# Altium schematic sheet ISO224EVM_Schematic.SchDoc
size 431 x 279 mm; Date: Not shown in title block; ApprovedBy: Not shown in title block; CheckedBy: Not shown in title block; Author: Not shown in title block; CompanyName: Not shown in title block; Engineer: Not shown in title block; Organization: Not shown in title block; Address1: Not shown in title block; Address2: Not shown in title block; Address3: Not shown in title block; Address4: Not shown in title block; DocumentNumber: 1; Revision: Use project parameter SCH_Rev; SheetNumber: 2; SheetTotal: 3; PageSetup: Record=PageOptions¦CenterHorizontal=True¦CenterVertical=True¦PrintScale=1.00¦XCorrection=1.00¦YCorrection=1.00¦PrintKind=0¦BorderSize=5000000¦LeftOffset=0¦BottomOffset=0¦Orientation=2¦PaperLength=1000¦PaperWidth=1000¦Scale=100¦PaperSource=15¦PrintQuality=600¦MediaType=1¦DitherType=10¦PaperKind=Letter¦PrintScaleMode=1
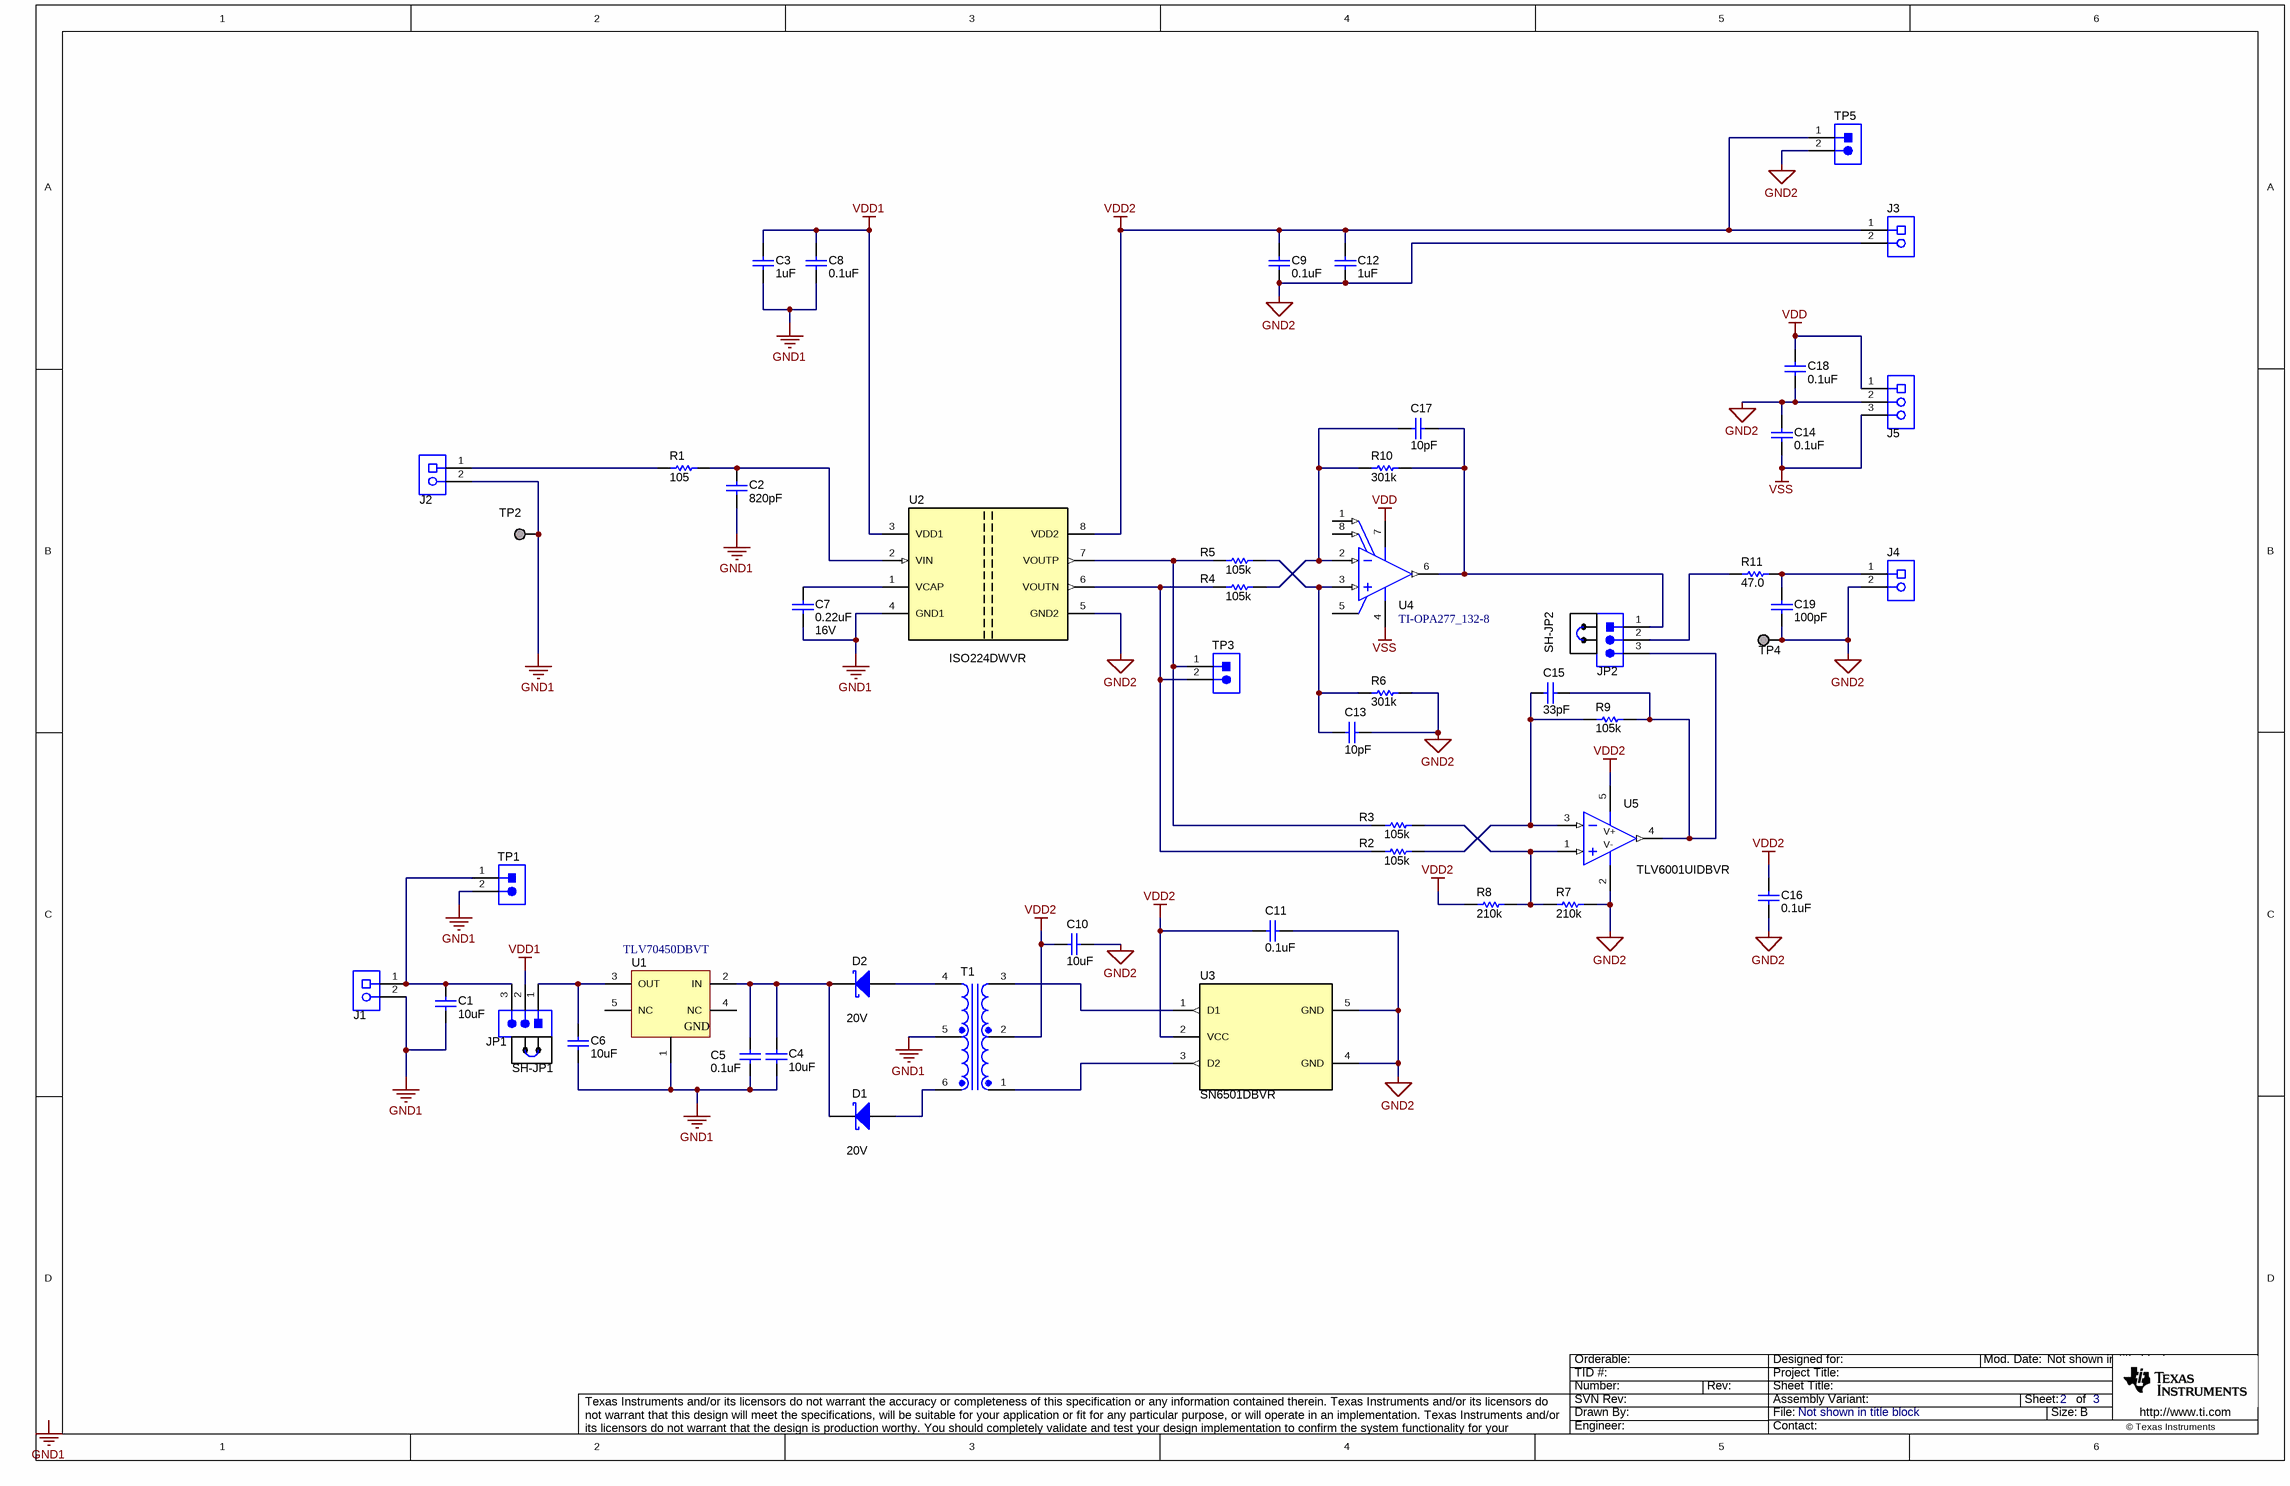
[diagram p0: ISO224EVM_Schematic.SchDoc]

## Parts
C1  ValueDisplayed: 10uF  [0805_HV]  (hidden comment: EMK212BJ106KG-T)
C2  ValueDisplayed: 820pF  [0805_HV]  (hidden comment: 08055A821JAT2A)
C3  ValueDisplayed: 1uF  [1206]  (hidden comment: 12063C105KAT2A)
C4  ValueDisplayed: 10uF  [0805_HV]  (hidden comment: EMK212BJ106KG-T)
C5  ValueDisplayed: 0.1uF  [0805_HV]  (hidden comment: C0805C104K3RACTU)
C6  ValueDisplayed: 10uF  [0805_HV]  (hidden comment: EMK212BJ106KG-T)
C7  ValueDisplayed: 0.22uF  VDC_V: 16V  [0603]  (hidden comment: 885012206048)
C8  ValueDisplayed: 0.1uF  [1206]  (hidden comment: 12061C104JAT2A)
C9  ValueDisplayed: 0.1uF  [1206]  (hidden comment: 12061C104JAT2A)
C10  ValueDisplayed: 10uF  [0805_HV]  (hidden comment: EMK212BJ106KG-T)
C11  ValueDisplayed: 0.1uF  [0603]  (hidden comment: 06033C104JAT2A)
C12  ValueDisplayed: 1uF  [1206]  (hidden comment: 12063C105KAT2A)
C13  ValueDisplayed: 10pF  [0603]  (hidden comment: C0603C100J5GACTU)
C14  ValueDisplayed: 0.1uF  [0603]  (hidden comment: 06033C104JAT2A)
C15  ValueDisplayed: 33pF  [0603]  (hidden comment: C0603C330J5GACTU)
C16  ValueDisplayed: 0.1uF  [0603]  (hidden comment: 06033C104JAT2A)
C17  ValueDisplayed: 10pF  [0603]  (hidden comment: C0603C100J5GACTU)
C18  ValueDisplayed: 0.1uF  [0603]  (hidden comment: 06033C104JAT2A)
C19  ValueDisplayed: 100pF  [0603]  (hidden comment: 0603ZC101KAT2A)
D1  value 20V  [SOD-123]  (hidden comment: MBR0520LT1G)
D2  value 20V  [SOD-123]  (hidden comment: MBR0520LT1G)
J1  ED555/2DS  [TERM_BLK_ED555-2DS]  (value not drawn)
J2  ED555/2DS  [TERM_BLK_ED555-2DS]  (value not drawn)
J3  ED555/2DS  [TERM_BLK_ED555-2DS]  (value not drawn)
J4  ED555/2DS  [TERM_BLK_ED555-2DS]  (value not drawn)
J5  ED555/3DS  [TERM_BLK_ED555-3DS]  (value not drawn)
JP1  TMM-103-01-T-S  [CONN_TMM-103-01-T-S]  (value not drawn)
JP2  TMM-103-01-T-S  [CONN_TMM-103-01-T-S]  (value not drawn)
R1  ValueDisplayed: 105  [0805_HV]  (hidden comment: CRCW0805105RFKEA)
R2  ValueDisplayed: 105k  [0603]  (hidden comment: CRCW0603105KFKEA)
R3  ValueDisplayed: 105k  [0603]  (hidden comment: CRCW0603105KFKEA)
R4  ValueDisplayed: 105k  [0603]  (hidden comment: CRCW0603105KFKEA)
R5  ValueDisplayed: 105k  [0603]  (hidden comment: CRCW0603105KFKEA)
R6  ValueDisplayed: 301k  [0603]  (hidden comment: CRCW0603301KFKEA)
R7  ValueDisplayed: 210k  [0603]  (hidden comment: RC0603FR-07210KL)
R8  ValueDisplayed: 210k  [0603]  (hidden comment: RC0603FR-07210KL)
R9  ValueDisplayed: 105k  [0603]  (hidden comment: CRCW0603105KFKEA)
R10  ValueDisplayed: 301k  [0603]  (hidden comment: CRCW0603301KFKEA)
R11  ValueDisplayed: 47.0  [0603]  (hidden comment: RC0603FR-0747RL)
SH-JP1  2SN-BK-G  [2SN-BK-G]  (value not drawn)
SH-JP2  2SN-BK-G  [2SN-BK-G]  (value not drawn)
T1  750313769  [WURTH_750313769]  (value not drawn)
TP1  TSW-102-07-G-S  [TSW-102-07-G-S]  (value not drawn)
TP2  1502-2  [Keystone1502-2]  (value not drawn)
TP3  TSW-102-07-G-S  [TSW-102-07-G-S]  (value not drawn)
TP4  1502-2  [Keystone1502-2]  (value not drawn)
TP5  TSW-102-07-G-S  [TSW-102-07-G-S]  (value not drawn)
U1  TLV70450DBVT  [DBV0005A_N]
U2  ISO224DWVR  [DWV0008A]
U3  SN6501DBVR  [DBV0005A_N]
U4  TI-OPA277_132-8  [D0008A_N]
U5  TLV6001UIDBVR  [DBV0005A_N]

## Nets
GND1: C1.2 C2.2 C3.2 C4.2 C5.2 C6.2 C7.2 C8.2 J1.2 J2.2 T1.5 TP1.2 TP2.1 U1.1(GND) U2.4(GND1)
GND2: C9.2 C10.1 C11.1 C12.2 C13.2 C14.2 C16.1 C18.1 C19.2 J3.2 J4.2 J5.2 R6.2 R7.2 TP4.1 TP5.2 U2.5(GND2) U3.4(GND) U3.5(GND) U5.2(V-)
VDD: C18.2 J5.1 U4.7(V+)
VDD1: C3.1 C8.1 JP1.2 U2.3(VDD1)
VDD2: C9.1 C10.2 C11.2 C12.1 C16.2 J3.1 R8.1 T1.2 TP5.1 U2.8(VDD2) U3.2(VCC) U5.5(V+)
VSS: C14.1 J5.3 U4.4(V-)
NetC1_1: C1.1 J1.1 JP1.3 TP1.1
NetC2_1: C2.1 R1.1 U2.2(VIN)
NetC4_1: C4.1 C5.1 D1.1(K) D2.1(K) U1.2(IN)
NetC6_1: C6.1 JP1.1 U1.3(OUT)
NetC7_1: C7.1 U2.1(VCAP)
NetC13_1: C13.1 R5.2 R6.1 U4.3(IN+)
NetC15_1: C15.1 R2.2 R9.1 U5.3(IN-)
NetC15_2: C15.2 JP2.3 R9.2 U5.4(OUT)
NetC17_1: C17.1 R4.2 R10.1 U4.2(IN-)
NetC17_2: C17.2 JP2.1 R10.2 U4.6(OUT)
NetC19_1: C19.1 J4.1 R11.2
NetD1_2: D1.2(A) T1.6
NetD2_2: D2.2(A) T1.4
NetJ2_1: J2.1 R1.2
NetJP2_2: JP2.2 R11.1
NetR2_1: R2.1 R4.1 TP3.2 U2.6(VOUTN)
NetR3_1: R3.1 R5.1 TP3.1 U2.7(VOUTP)
NetR3_2: R3.2 R7.1 R8.2 U5.1(IN+)
NetT1_1: T1.1 U3.3(D2)
NetT1_3: T1.3 U3.1(D1)

Not connected (* = marked no-connect by the designer): U1 4(NC) 5(NC); U4 1(OFFSET_TRIM) 5(NC) 8(OFFSET_TRIM)

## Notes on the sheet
- Labels drawn without touching a wire or pin: GND1

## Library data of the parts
C1 C4 C6 C10 = CMP-0008005-2: CAP, CERM, 10 uF, 16 V, +/- 10%, X5R, 0805; Manufacturer: Taiyo Yuden; Polarized: N; Value: 10uF; U/M: EA; Cap_F: 10µF; Value1: Unknown; VDC_V: 16V; TaMin_C: -55°C; TaMax_C: 85°C; Cap_Case: 0805; AEC Category: Q200; SizeArea_mm2: 2.5; SizeAreaWB_mm2: 6.75; SizeX_mm: 2; SizeY_mm: 1.25; SizeZ_mm: 1.45
C2 = CMP-0007626-2: CAP, CERM, 820 pF, 50 V, +/- 5%, C0G/NP0, 0805; Manufacturer: AVX; Polarized: N; Value: 820pF; U/M: EA; ESR_ohm: 1.23d; Value1: 0.123 ohm; VDC_V: 50V; TaMin_C: -55°C; TaMax_C: 125°C; Cap_Case: 0805; AEC Category: Q200; SizeArea_mm2: 2.5; SizeAreaWB_mm2: 6.75; SizeX_mm: 2; SizeY_mm: 1.25; SizeZ_mm: 1.45
C3 C12 = CMP-0008509-2: CAP, CERM, 1 uF, 25 V, +/- 10%, X7R, 1206; Manufacturer: AVX; Polarized: N; CompType: Capacitor; Value: 1uF; U/M: EA; Cap_F: 1µF; ESR_ohm: 0.013; Value1: 0.013 ohm; VDC_V: 25V; TaMin_C: -55°C; TaMax_C: 125°C; AEC Category: Q200; SizeArea_mm2: 5.12; SizeAreaWB_mm2: 10.92; SizeX_mm: 3.2; SizeY_mm: 1.6; SizeZ_mm: 1.35
C5 = CMP-0007723-2: CAP, CERM, 0.1 uF, 25 V, +/- 10%, X7R, 0805; Manufacturer: Kemet; Polarized: N; Value: 0.1uF; U/M: EA; Cap_F: 100nF; ESR_ohm: 0.064; Value1: 0.064 ohm; VDC_V: 25V; IRMS_A: 1.64A; TaMin_C: -55°C; TaMax_C: 125°C; Cap_Case: 0805; AEC Category: Q200; SizeArea_mm2: 2.5; SizeAreaWB_mm2: 6.75; SizeX_mm: 2; SizeY_mm: 1.25; SizeZ_mm: 1.45
C7 = CMP-0006830-4: CAP, CERM, 0.22 uF, 16 V, +/- 10%, X7R, 0603; Manufacturer: Wurth Elektronik; Polarized: N; Value: 0.22uF; U/M: EA; Cap_F: 220nF; Value1: Unknown; TaMin_C: -55°C; TaMax_C: 125°C; AEC Category: Q200; SizeArea_mm2: 1.28; SizeAreaWB_mm2: 4.68; SizeX_mm: 1.6; SizeY_mm: 0.8; SizeZ_mm: 1
C8 C9 = CMP-0008487-2: CAP, CERM, 0.1 uF, 100 V, +/- 5%, X7R, 1206; Manufacturer: AVX; Polarized: N; Value: 0.1uF; U/M: EA; Cap_F: 100nF; ESR_ohm: 0.037; Value1: 0.037 ohm; VDC_V: 100V; TaMin_C: -55°C; TaMax_C: 125°C; AEC Category: Q200; SizeArea_mm2: 5.12; SizeAreaWB_mm2: 10.92; SizeX_mm: 3.2; SizeY_mm: 1.6; SizeZ_mm: 1.35
C11 C14 C16 = CMP-0006752-5: CAP, CERM, 0.1 uF, 25 V, +/- 5%, X7R, 0603; Manufacturer: AVX; Polarized: N; CompType: Capacitor; Value: 0.1uF; U/M: EA; Cap_F: 100nF; ESR_ohm: 0.05; Value1: 0.05 ohm; VDC_V: 25V; TaMin_C: -55°C; TaMax_C: 125°C; SizeArea_mm2: 1.28; SizeAreaWB_mm2: 4.68; SizeX_mm: 1.6; SizeY_mm: 0.8; SizeZ_mm: 1; AEC Category: Q200
C13 C17 = CMP-0006839-4: CAP, CERM, 10 pF, 50 V, +/- 5%, C0G/NP0, 0603; Manufacturer: Kemet; Polarized: N; Value: 10pF; U/M: EA; Value1: Unknown; VDC_V: 50V; TaMin_C: -55°C; TaMax_C: 125°C; AEC Category: Q200; SizeArea_mm2: 1.28; SizeAreaWB_mm2: 4.68; SizeX_mm: 1.6; SizeY_mm: 0.8; SizeZ_mm: 1
C15 = CMP-0006919-4: CAP, CERM, 33 pF, 50 V, +/- 5%, C0G/NP0, 0603; Manufacturer: Kemet; Polarized: N; Value: 33pF; U/M: EA; Value1: Unknown; VDC_V: 50V; TaMin_C: -55°C; TaMax_C: 125°C; AEC Category: Q200; SizeArea_mm2: 1.28; SizeAreaWB_mm2: 4.68; SizeX_mm: 1.6; SizeY_mm: 0.8; SizeZ_mm: 1
C18 = CMP-0006752-5: CAP, CERM, 0.1 uF, 25 V, +/- 5%, X7R, 0603; Manufacturer: AVX; Polarized: N; Value: 0.1uF; U/M: EA; Cap_F: 100nF; ESR_ohm: 0.05; Value1: 0.05 ohm; VDC_V: 25V; TaMin_C: -55°C; TaMax_C: 125°C; SizeArea_mm2: 1.28; SizeAreaWB_mm2: 4.68; SizeX_mm: 1.6; SizeY_mm: 0.8; SizeZ_mm: 1; AEC Category: Q200
C19 = CMP-0006812-4: CAP, CERM, 100 pF, 10 V, +/- 10%, X7R, 0603; Manufacturer: AVX; Polarized: N; Value: 100pF; U/M: EA; Value1: Unknown; VDC_V: 10V; TaMin_C: -55°C; TaMax_C: 125°C; AEC Category: Q200; SizeArea_mm2: 1.28; SizeAreaWB_mm2: 4.68; SizeX_mm: 1.6; SizeY_mm: 0.8; SizeZ_mm: 1
D1 D2 = CMP-0028524-1: Diode, Schottky, 20 V, 0.5 A, SOD-123; Manufacturer: ON Semiconductor; U/M: EA; Vf_V: 3.85dV; Io_A: 5dA; Value1: 0.5A; Value2: 0.385V; TJmax_C: 125°C; RJC_CperW: 150; AEC Category: Q101; Green_Lifecycle: Active; Green_REACh: Passed; SizeArea_mm2: 6.545; SizeAreaWB_mm2: 13.095; SizeX_mm: 3.85; SizeY_mm: 1.7; SizeZ_mm: 1.35
J1-J4 = CMP-0074913-1: Terminal Block, 3.5mm Pitch, 2x1, TH; Manufacturer: On-Shore Technology; Pitch_mm: 3.5; Gender: Female; Shrouded: N; Row_Count: 1; ContactFinish: Brass; Current_A: 6A; Voltage_V: 150V; Cert_CULUS: Y; CNHeader: False; CT: True; Green_Lifecycle: Active; Green_REACh: Passed
J5 = CMP-0074916-1: Terminal Block, 3.5mm Pitch, 3x1, TH; Manufacturer: On-Shore Technology; Pitch_mm: 3.5; Gender: Female; Shrouded: N; Row_Count: 1; ContactFinish: Brass; Current_A: 6A; Voltage_V: 150V; Cert_CULUS: Y; CNHeader: False; CT: True; Green_Lifecycle: Active; Green_REACh: Passed
JP1 JP2 = CMP-0075452-1: Header, 2mm, 3x1, Tin, TH; Manufacturer: Samtec; CNHeader: True; CT: False; Green_Lifecycle: Active; Green_REACh: Passed
R1 = CMP-0020839-3: RES, 105, 1%, 0.125 W, AEC-Q200 Grade 0, 0805; Manufacturer: Vishay-Dale; Value: 105; Value_Code: 105R; Power_W: 125mW; Value2: 0.125W; VDC_V: 150V; TempCo: 100 ppm/C; SizeArea_mm2: 2.5; SizeX_mm: 2; SizeY_mm: 1.25; SizeZ_mm: 1.45; EIA_Code: E96; AEC Category: Q200; AEC Qualified: Y; AEC Grade: 0
R2-R5 R9 = CMP-0021994-4: RES, 105 k, 1%, 0.1 W, AEC-Q200 Grade 0, 0603; Manufacturer: Vishay-Dale; Value: 105k; Power_W: 100mW; Value2: 0.1W; VDC_V: 75V; TempCo: 100 ppm/C; SizeArea_mm2: 1.28; SizeX_mm: 1.6; SizeY_mm: 0.8; SizeZ_mm: 1; EIA_Code: E96; AEC Category: Q200; AEC Qualified: Y; AEC Grade: 0
R6 R10 = CMP-0022320-4: RES, 301 k, 1%, 0.1 W, AEC-Q200 Grade 0, 0603; Manufacturer: Vishay-Dale; Value: 301k; Power_W: 100mW; Value2: 0.1W; VDC_V: 75V; TempCo: 100 ppm/C; SizeArea_mm2: 1.28; SizeX_mm: 1.6; SizeY_mm: 0.8; SizeZ_mm: 1; EIA_Code: E96; AEC Category: Q200; AEC Qualified: Y; AEC Grade: 0
R7 R8 = CMP-0022909-2: RES, 210 k, 1%, 0.1 W, 0603; Manufacturer: Yageo America; Value: 210k; Power_W: 100mW; Value2: 0.1W; VDC_V: 150V; TempCo: 200 ppm/C; SizeArea_mm2: 1.28; SizeX_mm: 1.6; SizeY_mm: 0.8; SizeZ_mm: 1; EIA_Code: E96; U/M: EA; AEC Category: Q200
R11 = CMP-0023135-3: RES, 47.0, 1%, 0.1 W, 0603; Manufacturer: Yageo America; Value: 47.0; Res_ohm: 47; Value_Code: 47R0; Power_W: 100mW; Value2: 0.1W; VDC_V: 150V; TempCo: 200 ppm/C; SizeArea_mm2: 1.28; SizeX_mm: 1.6; SizeY_mm: 0.8; SizeZ_mm: 1; U/M: EA; AEC Category: Q200
SH-JP1 SH-JP2 = CMP-0003641-1: Shunt, 2mm, Gold plated, Black; Manufacturer: Samtec; Value: 1x2; Note: You can "mate" this to a header by matching the designator.  i.e. use SH-J3 for header J3
T1 = CMP-0030534-1: Transformer, 340uH, SMT; Manufacturer: Wurth Elektronik; DCR_ohm: 4.26d; Lp: 340; Ind_H: 340µH
TP1 TP3 TP5 = CMP-0075405-2: Header, 100mil, 2x1, Gold, TH; Manufacturer: Samtec; Pitch_mm: 2.54; Gender: Male; Shrouded: N; Row_Count: 1; Current_A: 6.3A; Voltage_V: 550V; Cert_CSA: Y; Green_Lifecycle: Active; Green_REACh: Passed
TP2 TP4 = CMP-0055113-1: Terminal, Turret, TH, Double; Manufacturer: Keystone; CompType: Turret Terminal; CNHeader: FALSE; Green_Lifecycle: Active; Green_REACh: Passed
U1 = CMP-0035561-1: Single Output LDO, 150 mA, Fixed 5 V Output, 2.5 to 24 V Input, with Ultra-Low IQ, 5-pin SOT-23 (DBV), -40 to 125 degC, Green (RoHS & no Sb/Br); Manufacturer: Texas Instruments; Accuracy(%): 2; Fixed Output Options(V): 5; Iout(Max)(A): 0.15; Iq(Typ)(mA): 0.003; SubFamily: Single Channel LDO; Vdo(Typ)(mV): 400; Vin(Max)(V): 24; Vin(Min)(V): 2.5
U2 = CMP-0077307-1: Reinforced Isolated Amplifier with Wide Input Voltage Range and Differential Output, DWV0008A (SOIC-8); Alternate Manufacturer: Texas Instruments; SizeAreaWB_mm2: 105.975; SizeZ_mm: 2.8; SizeX_mm: 11.5; SizeY_mm: 5.85; SizeArea_mm2: 67.275; CompType: IC; AEC Qualified: N; AEC Category: Q200
U3 = CMP-0065840-1: Low-Noise 350 mA, 410 kHz Transformer Driver, DBV0005A (SOT-23-5); Alternate PartNumber: SN6501DBVT; Manufacturer: Texas Instruments; CompType: IC; U/M: EA; Green_Lifecycle: Not Set; Green_REACh: Passed; SizeArea_mm2: 8.12; SizeAreaWB_mm2: 14.82; SizeX_mm: 2.8; SizeY_mm: 2.9; SizeZ_mm: 1.45
U4 = CMP-0040879-1: High Precision Operational Amplifier, 4 to 36 V, -40 to 85 degC, 8-pin SOIC (D8), Green (RoHS & no Sb/Br); Manufacturer: Texas Instruments; PartNumber: OPA277UA; CMRR(Min)(dB): 115; GBW(Typ)(MHz): 1; IIB(Max)(pA): 2800; Iq per channel(Max)(mA): 0.825; Offset Drift(Typ)(uV/C): 0.15; Packing: TUBE; Rating: Catalog; Slew Rate(Typ)(V/us): 0.8; Sub Family: High Supply Voltage Amplifier (>=30V), Low Noise Amp (<=10nV/rtHz), Low Offset Voltage Amplifier (<=500uV), Precision Amplifier; Total Supply Voltage(Max)(+5V is 5, +/-5V is 10): 36; Total Supply Voltage(Min)(+5V is 5, +/-5V is 10): 4; Vio (25C)(Max)(mV): 0.05
U5 = CMP-0073550-1: 1-MHz, Low-Power Operational Amplifier for Cost-Sensitive Systems, DBV0005A (SOT-23-5); Alternate PartNumber: TLV6001UIDBVT; Alternate Manufacturer: Texas Instruments; SizeAreaWB_mm2: 14.82; U/M: EA; SizeZ_mm: 1.45; SizeX_mm: 2.8; SizeY_mm: 2.9; SizeArea_mm2: 8.12; CompType: IC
